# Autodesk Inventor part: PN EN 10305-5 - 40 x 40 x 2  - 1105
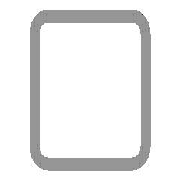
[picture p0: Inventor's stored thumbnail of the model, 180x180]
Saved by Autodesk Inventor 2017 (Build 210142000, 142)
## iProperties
IsCustomPart: 1
Created: 2016-02
Part Number: PN EN 10305-5 - 40 x 40 x 2  - 1105
Material: Stal, miękka
Description: Rury stalowe do zastosowań precyzyjnych -  (Część 5: Rury kwadratowe, spawane, wymiarowane na zimno)
Document SubType Name: Modeling
Standard: PN
Designer: X
Standards Organization: PN
Language: pl-PL
Size Designation: 40 x 40 x 2
Categories: <MemberInstance><Categories><Category DisplayName="Kształtowniki konstrukcyjne" InternalName="089c4875-fa83-4c05-b084-43b9cc11f5ed" Mnemonic="GRDR"><CategoryPar
Stock Number: 40 x 40 x 2
Density: 7.85 g/cm^3
Appearance: Częściowo polerowana
_CCFamilyMember: 26
_CCFamilyDisplayName: PN EN 10305-5 (Rury kwadratowe, spawane, wymiarowane na zimno) - Rury stalowe do zastosowań precyzyjnych -  (Część 5: Rury kwadratowe, spawane, wymiarowane na z
_FrameMemberDoc: Frame Member File
_Version: 15.0.0
_GetPNFromCC: 1
G_L: 1105,000 mm
G_W: 40,000 mm
G_H: 40,000 mm
Author: X
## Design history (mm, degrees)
node "Płaszczyzna początkowa"
node "Płaszczyzna końcowa"
sketch "Szkic"
  geometry: L1 (-20, -17)-(-20, 17); L2 (-17, 20)-(17, 20); L3 (20, 17)-(20, -17); L4 (17, -20)-(-17, -20); L5 (-17, 18)-(17, 18); L6 (18, 17)-(18, -17); L7 (17, -18)-(-17, -18); L8 (-18, -17)-(-18, 17); L9 (0, 28.87)-(0, -28.87) reference; L10 (-28.87, 0)-(28.87, 0) reference; A1 r 3 centre (-17, -17) between (-20, -17) and (-17, -20); A2 r 3 centre (-17, 17) between (-17, 20) and (-20, 17); A3 r 3 centre (17, 17) between (20, 17) and (17, 20); A4 r 3 centre (17, -17) between (17, -20) and (20, -17); A5 r 1 centre (-17, 17) between (-17, 18) and (-18, 17); A6 r 1 centre (17, 17) between (18, 17) and (17, 18); A7 r 1 centre (17, -17) between (17, -18) and (18, -17); A8 r 1 centre (-17, -17) between (-18, -17) and (-17, -18)
  constraints: 16 end point, 16 point on circle, 8 centre point, 8 tangent, 4 parallel, 3 equal radius, 2 perpendicular, 7 other
  dimensions: "d7" = 3 radius of A1 (= G_IR); "d10" = 40 distance between parallel lines of L2 L4 (= G_H); "d11" = 40 distance between parallel lines of L1 L3 (= G_W); "d12" = 2 distance between parallel lines of L3 L6 (= G_T); "d15" = 20 distance between parallel lines of L2 L10 (= 0.5 x d10); "d16" = 20 distance between parallel lines of L9 L3 (= 0.5 x d11)
extrude "Bryła" new body sketch "Szkic" stored distance "d3" = 1105 (= G_L); taper "d4" = 0 deg
node "Driven Length"
  sketch "Sketch3"
    geometry: L1 (0, 0)-(10, 0) reference
    constraints: 2 end point, 1 horizontal
  workplane "Work Plane3"
  sketch "Sketch4"
    geometry: L1 (-2, 35)-(12, 35) reference; L2 (-2, 1140)-(12, 1140) reference
    dimensions: "d18" = 1105 distance between parallel lines of L1 L2 (derived)
body "Solid1"
other parameters: "G_W" = 40 [user parameter; used in 1 equation term], "G_H" = 40 [user parameter; used in 1 equation term], "G_T" = 2 [user parameter; used in 1 equation term], "G_IR" = 3 [user parameter; used in 1 equation term], "G_L" = 1105 (= d18) [user parameter; used in 1 equation term], "G_OFFSET_START" = -35 [user parameter; used in 1 equation term], "G_OFFSET_END" = 0 [user parameter; used in 1 equation term], "d13" = 35 (= -G_OFFSET_START), "d17" = 90 deg
